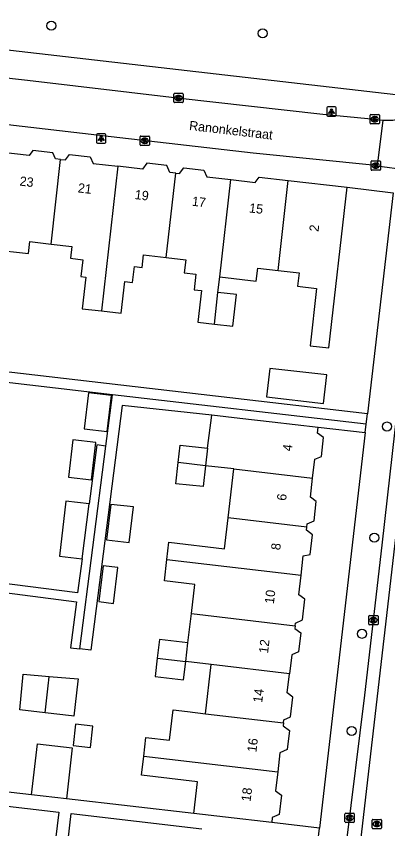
# Model space of a CAD drawing. Extents: x 161696 to 162377, y 380761 to 381673.
# Drawn here: x 162112.9 to 162152.7, y 381067.5 to 381154.7 of the extents above; entities that cross this region are included whole.
import ezdxf

# ---------------------------------------------------------------- set-up
doc = ezdxf.new("R2010")
doc.units = 0
for name, color, linetype in [('IMGEO_Boom', 7, 'Continuous'), ('IMGEO_Kolk', 7, 'Continuous'), ('IMGEO_Lichtpunt', 7, 'Continuous'), ('IMGEO_Openbare_ruimte_label', 7, 'Continuous'), ('IMGEO_Pand', 7, 'Continuous'), ('IMGEO_Pand_nummerreeks', 7, 'Continuous'), ('IMGEO_Rijbaan_lokaal_open', 7, 'Continuous'), ('IMGEO_Rioolput', 7, 'Continuous'), ('IMGEO_Voetpad_open', 7, 'Continuous')]:
    doc.layers.add(name, color=color, linetype=linetype)

msp = doc.modelspace()

# ---------------------------------------------------------------- linework, layer by layer
at = {"layer": 'IMGEO_Boom'}
for centre in [(162116.62, 381153.677), (162139.306, 381152.861), (162152.655, 381110.673), (162151.299, 381098.749), (162149.976, 381088.437), (162148.881, 381078)]:
    msp.add_circle(centre, 0.489, dxfattribs=at)
at = {"layer": 'IMGEO_Kolk'}
for p, q in [((162129.778, 381145.501), (162129.778, 381146.353)), ((162129.853, 381146.427), (162130.705, 381146.427)), ((162130.266, 381146.207), (162130.291, 381146.207)), ((162130.779, 381146.353), (162130.779, 381145.501)), ((162130.705, 381145.427), (162129.853, 381145.427)), ((162130.289, 381145.647), (162130.264, 381145.647)), ((162150.915, 381144.149), (162151.767, 381144.149)), ((162150.84, 381143.223), (162150.84, 381144.075)), ((162151.351, 381143.369), (162151.326, 381143.369)), ((162151.328, 381143.929), (162151.353, 381143.929)), ((162151.841, 381144.075), (162151.841, 381143.223)), ((162151.767, 381143.149), (162150.915, 381143.149)), ((162126.149, 381140.91), (162126.149, 381141.762)), ((162126.224, 381141.836), (162127.076, 381141.836)), ((162126.637, 381141.616), (162126.662, 381141.616)), ((162127.15, 381141.762), (162127.15, 381140.91)), ((162127.076, 381140.836), (162126.224, 381140.836)), ((162126.66, 381141.056), (162126.635, 381141.056)), ((162150.951, 381138.243), (162150.951, 381139.095)), ((162151.026, 381139.169), (162151.878, 381139.169)), ((162151.439, 381138.949), (162151.464, 381138.949)), ((162151.952, 381139.095), (162151.952, 381138.243)), ((162151.878, 381138.169), (162151.026, 381138.169)), ((162151.462, 381138.389), (162151.437, 381138.389)), ((162150.701, 381089.47), (162150.701, 381090.322)), ((162150.776, 381090.396), (162151.628, 381090.396)), ((162151.189, 381090.176), (162151.214, 381090.176)), ((162151.702, 381090.322), (162151.702, 381089.47)), ((162151.628, 381089.396), (162150.776, 381089.396)), ((162151.212, 381089.616), (162151.187, 381089.616)), ((162148.229, 381069.188), (162149.081, 381069.188)), ((162148.154, 381068.262), (162148.154, 381069.114)), ((162148.665, 381068.408), (162148.64, 381068.408)), ((162148.642, 381068.968), (162148.667, 381068.968)), ((162149.155, 381069.114), (162149.155, 381068.262)), ((162149.081, 381068.188), (162148.229, 381068.188))]:
    msp.add_line(p, q, dxfattribs=at)
for points in [[(162129.778, 381145.501), (162129.778, 381146.353)], [(162129.853, 381146.427), (162130.705, 381146.427)], [(162130.099, 381146.127), (162130.222, 381146.127), (162130.222, 381145.976), (162130.352, 381146.127), (162130.516, 381146.127), (162130.37, 381145.976), (162130.523, 381145.727), (162130.371, 381145.727), (162130.286, 381145.891), (162130.222, 381145.824), (162130.222, 381145.727), (162130.099, 381145.727), (162130.099, 381146.127)], [(162130.779, 381146.353), (162130.779, 381145.501)], [(162130.705, 381145.427), (162129.853, 381145.427)], [(162150.915, 381144.149), (162151.767, 381144.149)], [(162150.84, 381143.223), (162150.84, 381144.075)], [(162151.161, 381143.849), (162151.284, 381143.849), (162151.284, 381143.698), (162151.414, 381143.849), (162151.578, 381143.849), (162151.432, 381143.698), (162151.585, 381143.449), (162151.433, 381143.449), (162151.348, 381143.613), (162151.284, 381143.546), (162151.284, 381143.449), (162151.161, 381143.449), (162151.161, 381143.849)], [(162151.841, 381144.075), (162151.841, 381143.223)], [(162151.767, 381143.149), (162150.915, 381143.149)], [(162126.149, 381140.91), (162126.149, 381141.762)], [(162126.224, 381141.836), (162127.076, 381141.836)], [(162126.47, 381141.536), (162126.593, 381141.536), (162126.593, 381141.385), (162126.723, 381141.536), (162126.887, 381141.536), (162126.741, 381141.385), (162126.894, 381141.136), (162126.742, 381141.136), (162126.657, 381141.3), (162126.593, 381141.233), (162126.593, 381141.136), (162126.47, 381141.136), (162126.47, 381141.536)], [(162127.15, 381141.762), (162127.15, 381140.91)], [(162127.076, 381140.836), (162126.224, 381140.836)], [(162150.951, 381138.243), (162150.951, 381139.095)], [(162151.026, 381139.169), (162151.878, 381139.169)], [(162151.272, 381138.869), (162151.395, 381138.869), (162151.395, 381138.718), (162151.525, 381138.869), (162151.689, 381138.869), (162151.543, 381138.718), (162151.696, 381138.469), (162151.544, 381138.469), (162151.459, 381138.633), (162151.395, 381138.566), (162151.395, 381138.469), (162151.272, 381138.469), (162151.272, 381138.869)], [(162151.952, 381139.095), (162151.952, 381138.243)], [(162151.878, 381138.169), (162151.026, 381138.169)], [(162150.701, 381089.47), (162150.701, 381090.322)], [(162150.776, 381090.396), (162151.628, 381090.396)], [(162151.022, 381090.096), (162151.145, 381090.096), (162151.145, 381089.945), (162151.275, 381090.096), (162151.439, 381090.096), (162151.293, 381089.945), (162151.446, 381089.696), (162151.294, 381089.696), (162151.209, 381089.86), (162151.145, 381089.793), (162151.145, 381089.696), (162151.022, 381089.696), (162151.022, 381090.096)], [(162151.702, 381090.322), (162151.702, 381089.47)], [(162151.628, 381089.396), (162150.776, 381089.396)], [(162148.229, 381069.188), (162149.081, 381069.188)], [(162148.154, 381068.262), (162148.154, 381069.114)], [(162148.475, 381068.888), (162148.598, 381068.888), (162148.598, 381068.737), (162148.728, 381068.888), (162148.892, 381068.888), (162148.746, 381068.737), (162148.899, 381068.488), (162148.747, 381068.488), (162148.662, 381068.652), (162148.598, 381068.585), (162148.598, 381068.488), (162148.475, 381068.488), (162148.475, 381068.888)], [(162149.155, 381069.114), (162149.155, 381068.262)], [(162149.081, 381068.188), (162148.229, 381068.188)]]:
    msp.add_lwpolyline(points, dxfattribs=at)
for centre, start, end in [((162129.855, 381146.351), 91.55205, 178.44795), ((162129.855, 381146.351), 91.55205, 178.44795), ((162130.703, 381146.351), 1.55205, 88.44795), ((162130.703, 381146.351), 1.55205, 88.44795), ((162129.855, 381145.503), 181.55205, 268.44795), ((162129.855, 381145.503), 181.55205, 268.44795), ((162130.703, 381145.503), 271.55205, 358.44795), ((162130.703, 381145.503), 271.55205, 358.44795), ((162150.917, 381144.073), 91.55205, 178.44795), ((162150.917, 381144.073), 91.55205, 178.44795), ((162151.765, 381144.073), 1.55205, 88.44795), ((162151.765, 381144.073), 1.55205, 88.44795), ((162150.917, 381143.225), 181.55205, 268.44795), ((162150.917, 381143.225), 181.55205, 268.44795), ((162151.765, 381143.225), 271.55205, 358.44795), ((162151.765, 381143.225), 271.55205, 358.44795), ((162126.226, 381141.76), 91.55205, 178.44795), ((162126.226, 381141.76), 91.55205, 178.44795), ((162127.074, 381141.76), 1.55205, 88.44795), ((162127.074, 381141.76), 1.55205, 88.44795), ((162126.226, 381140.912), 181.55205, 268.44795), ((162126.226, 381140.912), 181.55205, 268.44795), ((162127.074, 381140.912), 271.55205, 358.44795), ((162127.074, 381140.912), 271.55205, 358.44795), ((162151.028, 381139.093), 91.55205, 178.44795), ((162151.028, 381139.093), 91.55205, 178.44795), ((162151.876, 381139.093), 1.55205, 88.44795), ((162151.876, 381139.093), 1.55205, 88.44795), ((162151.028, 381138.245), 181.55205, 268.44795), ((162151.028, 381138.245), 181.55205, 268.44795), ((162151.876, 381138.245), 271.55205, 358.44795), ((162151.876, 381138.245), 271.55205, 358.44795), ((162150.778, 381090.32), 91.55205, 178.44795), ((162150.778, 381090.32), 91.55205, 178.44795), ((162151.626, 381090.32), 1.55205, 88.44795), ((162151.626, 381090.32), 1.55205, 88.44795), ((162150.778, 381089.472), 181.55205, 268.44795), ((162150.778, 381089.472), 181.55205, 268.44795), ((162151.626, 381089.472), 271.55205, 358.44795), ((162151.626, 381089.472), 271.55205, 358.44795), ((162148.231, 381069.112), 91.55205, 178.44795), ((162148.231, 381069.112), 91.55205, 178.44795), ((162149.079, 381069.112), 1.55205, 88.44795), ((162149.079, 381069.112), 1.55205, 88.44795), ((162148.231, 381068.264), 181.55205, 268.44795), ((162148.231, 381068.264), 181.55205, 268.44795), ((162149.079, 381068.264), 271.55205, 358.44795), ((162149.079, 381068.264), 271.55205, 358.44795)]:
    msp.add_arc(centre, 0.0765, start, end, dxfattribs=at)
for centre, major_axis, ratio, start_param, end_param in [((162130.265, 381145.927), (-0.387, 0.002), 0.722429, 4.712389, 7.853982), ((162130.29, 381145.927), (-0.39, 0.002), 0.717154, 1.570796, 4.712389), ((162151.327, 381143.649), (-0.387, 0.002), 0.722429, 4.712389, 7.853982), ((162151.352, 381143.649), (-0.39, 0.002), 0.717154, 1.570796, 4.712389), ((162126.636, 381141.336), (-0.387, 0.002), 0.722429, 4.712389, 7.853982), ((162126.661, 381141.336), (-0.39, 0.002), 0.717154, 1.570796, 4.712389), ((162151.438, 381138.669), (-0.387, 0.002), 0.722429, 4.712389, 7.853982), ((162151.463, 381138.669), (-0.39, 0.002), 0.717154, 1.570796, 4.712389), ((162151.188, 381089.896), (-0.387, 0.002), 0.722429, 4.712389, 7.853982), ((162151.213, 381089.896), (-0.39, 0.002), 0.717154, 1.570796, 4.712389), ((162148.641, 381068.688), (-0.387, 0.002), 0.722429, 4.712389, 7.853982), ((162148.666, 381068.688), (-0.39, 0.002), 0.717154, 1.570796, 4.712389)]:
    msp.add_ellipse(centre, major_axis=major_axis, ratio=ratio, start_param=start_param, end_param=end_param, dxfattribs=at)
at = {"layer": 'IMGEO_Lichtpunt'}
for p, q in [((162146.206, 381144.872), (162146.206, 381144.065)), ((162146.206, 381144.872), (162146.206, 381144.065)), ((162147.108, 381144.967), (162146.3, 381144.967)), ((162147.108, 381144.967), (162146.3, 381144.967)), ((162147.202, 381144.065), (162147.202, 381144.872)), ((162147.202, 381144.065), (162147.202, 381144.872)), ((162146.3, 381143.971), (162147.108, 381143.971)), ((162146.3, 381143.971), (162147.108, 381143.971)), ((162121.476, 381141.974), (162121.476, 381141.167)), ((162121.476, 381141.974), (162121.476, 381141.167)), ((162122.378, 381142.069), (162121.57, 381142.069)), ((162122.378, 381142.069), (162121.57, 381142.069)), ((162122.472, 381141.167), (162122.472, 381141.974)), ((162122.472, 381141.167), (162122.472, 381141.974)), ((162121.57, 381141.073), (162122.378, 381141.073)), ((162121.57, 381141.073), (162122.378, 381141.073))]:
    msp.add_line(p, q, dxfattribs=at)
for points in [[(162146.58, 381144.536), (162146.619, 381144.508), (162146.431, 381144.246), (162146.393, 381144.273), (162146.58, 381144.536)], [(162146.682, 381144.488), (162146.729, 381144.488), (162146.729, 381144.166), (162146.682, 381144.166), (162146.682, 381144.488)], [(162146.792, 381144.508), (162146.83, 381144.535), (162147.017, 381144.273), (162146.978, 381144.245), (162146.792, 381144.508)], [(162121.85, 381141.638), (162121.889, 381141.61), (162121.701, 381141.348), (162121.663, 381141.375), (162121.85, 381141.638)], [(162121.952, 381141.59), (162121.999, 381141.59), (162121.999, 381141.268), (162121.952, 381141.268), (162121.952, 381141.59)], [(162122.062, 381141.61), (162122.1, 381141.637), (162122.287, 381141.375), (162122.248, 381141.347), (162122.062, 381141.61)]]:
    msp.add_lwpolyline(points, dxfattribs=at)
for centre in [(162146.705, 381144.67), (162121.975, 381141.772)]:
    msp.add_circle(centre, 0.0994, dxfattribs=at)
for centre, start, end in [((162146.3, 381144.872), 90, 180), ((162146.3, 381144.872), 90, 180), ((162147.108, 381144.872), 0, 90), ((162147.108, 381144.872), 0, 90), ((162146.3, 381144.065), 180, 270), ((162146.3, 381144.065), 180, 270), ((162147.108, 381144.065), 270, 0), ((162147.108, 381144.065), 270, 360), ((162121.57, 381141.974), 90, 180), ((162121.57, 381141.974), 90, 180), ((162122.378, 381141.974), 0, 90), ((162122.378, 381141.974), 0, 90), ((162121.57, 381141.167), 180, 270), ((162121.57, 381141.167), 180, 270), ((162122.378, 381141.167), 270, 0), ((162122.378, 381141.167), 270, 360)]:
    msp.add_arc(centre, 0.0946, start, end, dxfattribs=at)
at = {"layer": 'IMGEO_Pand'}
for points in [[(162117.619, 381139.339), (162117.069, 381139.402), (162116.786, 381140.052), (162114.638, 381140.296), (162114.23, 381139.744), (162111.418, 381140.063)], [(162117.619, 381139.339), (162118.151, 381139.279), (162118.58, 381139.86), (162120.811, 381139.607), (162121.118, 381138.9), (162123.777, 381138.598)], [(162116.589, 381130.252), (162117.619, 381139.339)], [(162129.974, 381137.857), (162129.348, 381137.928), (162129.021, 381138.677), (162126.89, 381138.919), (162126.43, 381138.297), (162123.777, 381138.598)], [(162123.777, 381138.598), (162122.016, 381123.075)], [(162129.974, 381137.857), (162130.377, 381137.811), (162130.834, 381138.428), (162132.992, 381138.183), (162133.309, 381137.455), (162135.888, 381137.162)], [(162128.947, 381128.802), (162129.974, 381137.857)], [(162134.704, 381126.73), (162135.888, 381137.162)], [(162135.888, 381137.162), (162138.522, 381136.863), (162138.941, 381137.429), (162142.069, 381137.074)], [(162140.973, 381127.411), (162142.069, 381137.074)], [(162140.973, 381127.411), (162143.231, 381127.155), (162143.069, 381125.726), (162145.098, 381125.495), (162144.4, 381119.344), (162146.43, 381119.113), (162148.389, 381136.356)], [(162142.069, 381137.074), (162148.389, 381136.356)], [(162110.241, 381129.686), (162114.163, 381129.244), (162114.308, 381130.511), (162116.589, 381130.252)], [(162116.589, 381130.252), (162118.836, 381129.997), (162118.694, 381128.74), (162120.015, 381128.569), (162119.782, 381126.767), (162120.325, 381126.704), (162119.932, 381123.317), (162122.016, 381123.075)], [(162122.016, 381123.075), (162124.118, 381122.831), (162124.511, 381126.218), (162125.333, 381126.123), (162125.557, 381127.851), (162126.371, 381127.746), (162126.509, 381129.079), (162128.947, 381128.802)], [(162128.947, 381128.802), (162131.073, 381128.56), (162130.902, 381127.167), (162132.148, 381127.024), (162131.958, 381125.353), (162132.756, 381125.26), (162132.363, 381121.871), (162134.13, 381121.666)], [(162134.704, 381126.73), (162138.629, 381126.279), (162138.797, 381127.658), (162140.973, 381127.411)], [(162134.515, 381125.056), (162134.704, 381126.73)], [(162134.13, 381121.666), (162134.515, 381125.056)], [(162134.13, 381121.666), (162136.119, 381121.436), (162136.512, 381124.824), (162134.515, 381125.056)], [(162146.19, 381116.206), (162140.092, 381116.918), (162139.734, 381113.847), (162145.832, 381113.136), (162146.19, 381116.206)], [(162120.161, 381110.433), (162122.622, 381110.146), (162123.07, 381113.996), (162120.609, 381114.283), (162120.161, 381110.433)], [(162133.39, 381108.347), (162133.856, 381111.905)], [(162133.856, 381111.905), (162133.859, 381111.929), (162136.865, 381111.589), (162140.325, 381111.185), (162145.291, 381110.606)], [(162144.677, 381105.13), (162144.913, 381107.155), (162145.625, 381107.462), (162145.862, 381109.497), (162145.217, 381109.977), (162145.291, 381110.606)], [(162118.473, 381105.247), (162120.945, 381104.959), (162121.412, 381108.963), (162118.94, 381109.251), (162118.473, 381105.247)], [(162130.244, 381106.817), (162130.446, 381108.668), (162133.39, 381108.347)], [(162133.39, 381108.347), (162133.186, 381106.474)], [(162133.186, 381106.474), (162132.941, 381104.222), (162129.997, 381104.543), (162130.244, 381106.817)], [(162133.186, 381106.474), (162130.244, 381106.817)], [(162136.227, 381106.118), (162133.186, 381106.474)], [(162135.616, 381100.871), (162136.227, 381106.118)], [(162136.227, 381106.118), (162144.677, 381105.13)], [(162144.046, 381099.885), (162144.087, 381100.231), (162144.826, 381100.55), (162145.069, 381102.638), (162144.441, 381103.106), (162144.677, 381105.13)], [(162120.692, 381102.382), (162118.173, 381102.676), (162117.486, 381096.778), (162119.927, 381096.494)], [(162119.927, 381096.494), (162120.692, 381102.382)], [(162122.557, 381098.531), (162124.992, 381098.247), (162125.434, 381102.04), (162122.999, 381102.324), (162122.557, 381098.531)], [(162129.035, 381096.394), (162129.256, 381098.264), (162135.23, 381097.559), (162135.616, 381100.871)], [(162144.046, 381099.885), (162135.616, 381100.871)], [(162143.437, 381094.71), (162143.679, 381096.788), (162144.403, 381096.929), (162144.651, 381099.059), (162144.006, 381099.539), (162144.046, 381099.885)], [(162131.67, 381090.603), (162132.04, 381093.736), (162128.767, 381094.122), (162129.035, 381096.394)], [(162129.035, 381096.394), (162143.437, 381094.71)], [(162121.735, 381091.887), (162123.301, 381091.702), (162123.753, 381095.531), (162122.187, 381095.716), (162121.735, 381091.887)], [(162142.812, 381089.3), (162142.846, 381089.59), (162143.6, 381089.916), (162143.859, 381092.136), (162143.194, 381092.63), (162143.437, 381094.71)], [(162131.297, 381087.448), (162131.67, 381090.603)], [(162131.67, 381090.603), (162142.812, 381089.3)], [(162142.812, 381089.3), (162142.778, 381089.01), (162143.407, 381088.542), (162143.169, 381086.503), (162142.431, 381086.184), (162142.193, 381084.14)], [(162131.297, 381087.448), (162128.225, 381087.811), (162127.988, 381085.803)], [(162131.061, 381085.445), (162131.297, 381087.448)], [(162127.988, 381085.803), (162127.759, 381083.859), (162130.831, 381083.496), (162131.061, 381085.445)], [(162127.988, 381085.803), (162131.061, 381085.445)], [(162133.78, 381085.124), (162131.061, 381085.445)], [(162133.167, 381079.863), (162133.78, 381085.124)], [(162142.193, 381084.14), (162133.78, 381085.124)], [(162115.951, 381079.962), (162113.246, 381080.275), (162113.589, 381084.09), (162116.4, 381083.85)], [(162141.563, 381078.882), (162141.602, 381079.212), (162142.314, 381079.52), (162142.561, 381081.642), (162141.954, 381082.093), (162142.193, 381084.14)], [(162116.4, 381083.85), (162119.494, 381083.585), (162119.468, 381083.357), (162119.035, 381079.607), (162118.803, 381079.633), (162115.951, 381079.962)], [(162115.951, 381079.962), (162116.321, 381083.163), (162116.356, 381083.468), (162116.4, 381083.85)], [(162126.548, 381075.31), (162126.785, 381077.319), (162129.322, 381077.019), (162129.701, 381080.267), (162131.255, 381080.086), (162133.167, 381079.863)], [(162133.167, 381079.863), (162141.563, 381078.882)], [(162118.968, 381076.454), (162120.821, 381076.24), (162121.085, 381078.53), (162119.232, 381078.744), (162118.968, 381076.454)], [(162141.563, 381078.882), (162141.525, 381078.556), (162142.194, 381078.058), (162141.957, 381076.018), (162141.169, 381075.678), (162140.93, 381073.628)], [(162114.505, 381071.152), (162115.131, 381076.635), (162118.863, 381076.209), (162118.237, 381070.726)], [(162131.918, 381069.148), (162132.317, 381072.568), (162126.308, 381073.277), (162126.548, 381075.31)], [(162126.548, 381075.31), (162140.93, 381073.628)], [(162140.93, 381073.628), (162140.69, 381071.576), (162141.326, 381071.103), (162141.085, 381069.035), (162140.35, 381068.718), (162140.287, 381068.173)], [(162118.237, 381070.726), (162114.505, 381071.152)], [(162140.287, 381068.173), (162135.321, 381068.752), (162131.918, 381069.148)]]:
    msp.add_lwpolyline(points, dxfattribs=at)
at = {"layer": 'IMGEO_Rijbaan_lokaal_open'}
for points in [[(162037.977, 381156.569), (162045.02, 381155.742), (162057.292, 381154.376), (162070.622, 381152.857), (162083.704, 381151.361), (162088.985, 381150.738), (162099.359, 381149.494), (162114.073, 381147.824), (162130.147, 381145.94), (162145.788, 381144.184), (162151.341, 381143.648), (162152.215, 381143.559)], [(162151.612, 381138.643), (162151.448, 381138.67), (162138.28, 381140.018), (162123.06, 381141.745), (162110.364, 381143.24), (162099.301, 381144.492)], [(162152.215, 381143.559), (162151.612, 381138.643)], [(162151.612, 381138.643), (162154.785, 381138.216)], [(162149.756, 381065.313), (162157.702, 381134.076)]]:
    msp.add_lwpolyline(points, dxfattribs=at)
msp.add_arc((162152.754, 381148.616), 5.085, 263.9214, 328.66286, dxfattribs=at)
at = {"layer": 'IMGEO_Rioolput'}
for p, q in [((162151.071, 381067.598), (162151.071, 381068.45)), ((162151.146, 381068.524), (162151.998, 381068.524)), ((162151.559, 381068.304), (162151.584, 381068.304)), ((162152.072, 381068.45), (162152.072, 381067.598)), ((162151.998, 381067.524), (162151.146, 381067.524)), ((162151.582, 381067.744), (162151.557, 381067.744))]:
    msp.add_line(p, q, dxfattribs=at)
for points in [[(162151.071, 381067.598), (162151.071, 381068.45)], [(162151.146, 381068.524), (162151.998, 381068.524)], [(162152.072, 381068.45), (162152.072, 381067.598)], [(162151.998, 381067.524), (162151.146, 381067.524)], [(162151.66, 381068.222), (162151.408, 381068.224), (162151.408, 381067.824)], [(162151.408, 381067.824), (162151.532, 381067.824), (162151.532, 381067.986), (162151.543, 381067.986)], [(162151.586, 381068.143), (162151.532, 381068.143), (162151.532, 381068.062)], [(162151.532, 381068.062), (162151.584, 381068.062)], [(162151.59, 381067.957), (162151.661, 381067.824), (162151.801, 381067.824), (162151.736, 381067.95)]]:
    msp.add_lwpolyline(points, dxfattribs=at)
for centre, radius, start, end in [((162151.148, 381068.448), 0.0765, 91.55205, 178.44795), ((162151.148, 381068.448), 0.0765, 91.55205, 178.44795), ((162151.996, 381068.448), 0.0765, 1.55205, 88.44795), ((162151.996, 381068.448), 0.0765, 1.55205, 88.44795), ((162151.148, 381067.6), 0.0765, 181.55205, 268.44795), ((162151.148, 381067.6), 0.0765, 181.55205, 268.44795), ((162151.542, 381067.933), 0.0533, 26.02933, 88.69889), ((162151.568, 381068.251), 0.19, 274.7715, 282.96867), ((162151.592, 381068.047), 0.0964, 77.00612, 93.18647), ((162151.606, 381068.104), 0.0378, 276.66336, 79.67722), ((162151.659, 381068.112), 0.109, 350.36119, 89.41601), ((162151.657, 381068.112), 0.112, 277.58423, 350.98172), ((162151.641, 381067.897), 0.108, 29.51342, 73.79051), ((162151.996, 381067.6), 0.0765, 271.55205, 358.44795), ((162151.996, 381067.6), 0.0765, 271.55205, 358.44795)]:
    msp.add_arc(centre, radius, start, end, dxfattribs=at)
for centre, major_axis, ratio, start_param, end_param in [((162151.558, 381068.024), (-0.387, 0.002), 0.722429, 4.712389, 7.853982), ((162151.583, 381068.024), (-0.39, 0.002), 0.717154, 1.570796, 4.712389)]:
    msp.add_ellipse(centre, major_axis=major_axis, ratio=ratio, start_param=start_param, end_param=end_param, dxfattribs=at)
at = {"layer": 'IMGEO_Voetpad_open'}
for points in [[(162105.038, 381151.871), (162154.533, 381146.175)], [(162148.389, 381136.356), (162153.313, 381135.753)], [(162153.313, 381135.753), (162150.568, 381112.043)], [(162150.568, 381112.043), (162104.656, 381117.359), (162102.759, 381117.558)], [(162123.177, 381114.087), (162108.158, 381115.826)], [(162122.47, 381108.579), (162123.177, 381114.087)], [(162150.439, 381110.931), (162123.177, 381114.087)], [(162133.856, 381111.905), (162124.236, 381112.916), (162120.872, 381086.689), (162119.678, 381086.815)], [(162149.229, 381065.849), (162148.321, 381065.955), (162150.269, 381081.843), (162152.135, 381097.939), (162153.833, 381112.868)], [(162150.439, 381110.931), (162150.568, 381112.043)], [(162145.291, 381110.606), (162150.334, 381110.022)], [(162150.334, 381110.022), (162150.439, 381110.931)], [(162150.334, 381110.022), (162145.42, 381067.579)], [(162119.678, 381086.815), (162122.47, 381108.579)], [(162122.47, 381108.579), (162121.513, 381108.701), (162120.692, 381102.382)], [(162119.927, 381096.494), (162119.45, 381092.824), (162102.019, 381095.06)], [(162101.91, 381094.116), (162119.328, 381091.882), (162118.683, 381086.919), (162119.678, 381086.815)], [(162114.505, 381071.152), (162103.217, 381072.458)], [(162101.193, 381071.182), (162117.423, 381069.291), (162117.083, 381066.376)], [(162131.918, 381069.148), (162118.237, 381070.726)], [(162118.421, 381066.332), (162118.748, 381069.136), (162132.798, 381067.511)], [(162145.42, 381067.579), (162140.287, 381068.173)], [(162145.245, 381066.064), (162145.42, 381067.579)]]:
    msp.add_lwpolyline(points, dxfattribs=at)

# ---------------------------------------------------------------- texts
at = {"layer": 'IMGEO_Openbare_ruimte_label'}
msp.add_text('Ranonkelstraat', height=1, rotation=353.39397, dxfattribs=at).set_placement((162131.382, 381142.495))
at = {"layer": 'IMGEO_Pand_nummerreeks'}
for s, rotation, p in [('23', 353.33383, (162113.179, 381136.534)), ('21', 353.33383, (162119.429, 381135.803)), ('19', 353.33383, (162125.544, 381135.089)), ('17', 353.33383, (162131.682, 381134.372)), ('15', 353.33383, (162137.82, 381133.654)), ('2', 83.51834, (162145.305, 381131.534)), ('4', 83.27369, (162142.444, 381107.976)), ('6', 83.27434, (162141.819, 381102.672)), ('8', 83.27434, (162141.193, 381097.372)), ('10', 83.27434, (162140.513, 381091.609)), ('12', 83.27369, (162139.886, 381086.299)), ('14', 83.27434, (162139.262, 381080.998)), ('16', 83.27369, (162138.636, 381075.694)), ('18', 83.27369, (162138.011, 381070.393))]:
    msp.add_text(s, height=1, rotation=rotation, dxfattribs=at).set_placement(p)

doc.saveas('drawing.dxf')
